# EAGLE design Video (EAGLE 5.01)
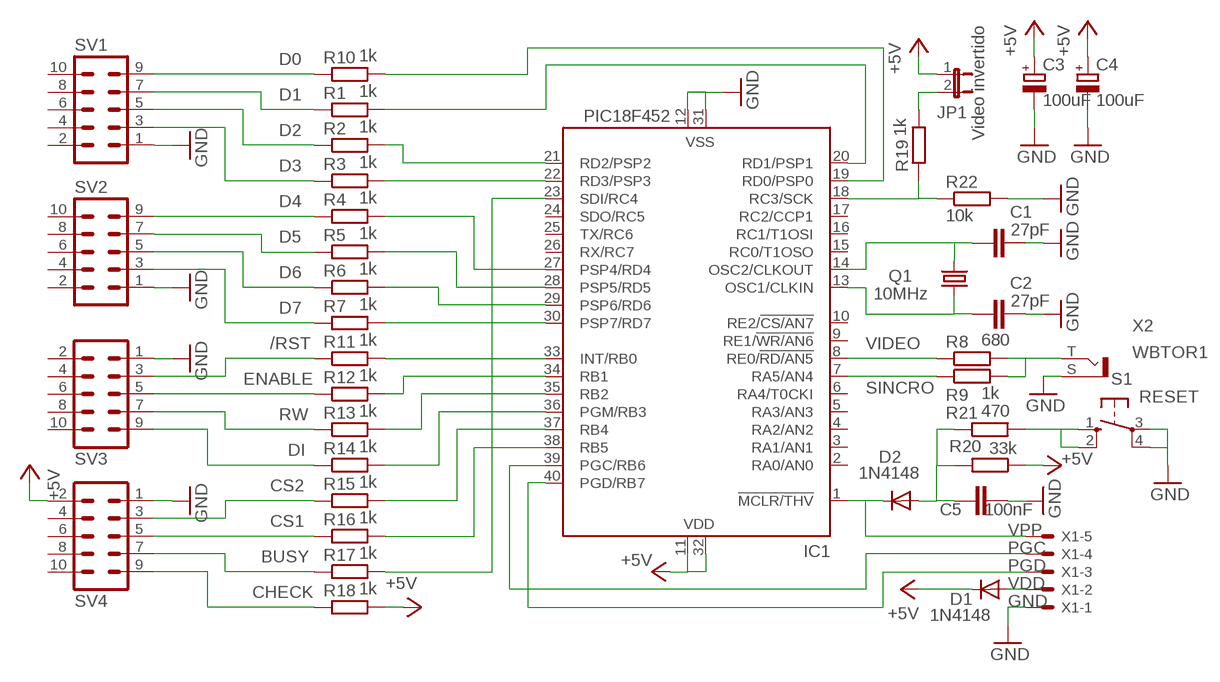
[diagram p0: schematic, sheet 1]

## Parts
C1  27pF  C-EU050-025X075  [C050-025X075]
C2  27pF  C-EU050-025X075  [C050-025X075]
C3  100uF  CPOL-EUE2-5  [E2-5]
C4  100uF  CPOL-EUE2-5  [E2-5]
C5  100nF  C-EU050-025X075  [C050-025X075]
D1  1N4148  [DO35-10]
D2  1N4148  [DO35-10]
IC1  PIC18F452  PIC16F877P  [DIL40]
JP1  Video invertido  JP1E  [JP1]
Q1  10MHz  CRYSTALHC49U-V  [HC49U-V]
R1  1k  R-EU_0207/12  [0207/12]
R2  1k  R-EU_0207/12  [0207/12]
R3  1k  R-EU_0207/12  [0207/12]
R4  1k  R-EU_0207/12  [0207/12]
R5  1k  R-EU_0207/12  [0207/12]
R6  1k  R-EU_0207/12  [0207/12]
R7  1k  R-EU_0207/12  [0207/12]
R8  680  R-EU_0207/12  [0207/12]
R9  1k  R-EU_0207/12  [0207/12]
R10  1k  R-EU_0207/12  [0207/12]
R11  1k  R-EU_0207/12  [0207/12]
R12  1k  R-EU_0207/12  [0207/12]
R13  1k  R-EU_0207/12  [0207/12]
R14  1k  R-EU_0207/12  [0207/12]
R15  1k  R-EU_0207/12  [0207/12]
R16  1k  R-EU_0207/12  [0207/12]
R17  1k  R-EU_0207/12  [0207/12]
R18  1k  R-EU_0207/12  [0207/12]
R19  1k  R-EU_0207/12  [0207/12]
R20  33k  R-EU_0207/12  [0207/12]
R21  470  R-EU_0207/12  [0207/12]
R22  10k  R-EU_0207/12  [0207/12]
S1  RESET  10-XX  [B3F-10XX]
SV1  ML10  [ML10]
SV2  ML10  [ML10]
SV3  ML10  [ML10]
SV4  ML10  [ML10]
X1  22-23-2051  [22-23-2051]
X2  WBTOR1  [WBTOR1]

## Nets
+5V: C3.+ C4.+ D1.C IC1.11(VDD) IC1.32(VDD) JP1.1 R18.2 R20.1 SV4.2
/RST: R11.1 SV3.3
BUSY: R17.1 SV4.7
CHECK: R18.1 SV4.9
CS1: R16.1 SV4.5
CS2: R15.1 SV4.3
D0: R10.1 SV1.9
D1: R1.1 SV1.7
D2: R2.1 SV1.5
D3: R3.1 SV1.3
D4: R4.1 SV2.9
D5: R5.1 SV2.7
D6: R6.1 SV2.5
D7: R7.1 SV2.3
DI: R14.1 SV3.9
ENABLE: R12.1 SV3.5
GND: C1.2 C2.2 C3.- C4.- C5.2 IC1.12(VSS) IC1.31(VSS) R22.2 S1.3(P) S1.4(P1) SV1.1 SV2.1 SV3.1 SV4.1 X1.1 X2.S
N$1: IC1.19(RD0/PSP0) R10.2
N$2: IC1.20(RD1/PSP1) R1.2
N$3: IC1.28(PSP5/RD5) R5.2
N$4: IC1.22(RD3/PSP3) R3.2
N$5: IC1.27(PSP4/RD4) R4.2
N$6: IC1.23(SDI/RC4) R17.2
N$7: IC1.29(PSP6/RD6) R6.2
N$8: IC1.30(PSP7/RD7) R7.2
N$9: IC1.21(RD2/PSP2) R2.2
N$10: C1.1 IC1.14(OSC2/CLKOUT) Q1.2
N$11: IC1.33(INT/RB0) R11.2
N$14: R8.2 R9.2 X2.T
N$15: IC1.34(RB1) R12.2
N$16: IC1.35(RB2) R13.2
N$17: IC1.36(PGM/RB3) R14.2
N$18: IC1.37(RB4) R15.2
N$19: IC1.38(RB5) R16.2
N$20: C2.1 IC1.13(OSC1/CLKIN) Q1.1
N$22: IC1.18(RC3/SCK) R19.1 R22.1
N$23: JP1.2 R19.2
N$27: C5.1 D2.A R20.2 R21.1
N$28: R21.2 S1.1(S) S1.2(S1)
PGC: IC1.39(PGC/RB6) X1.4
PGD: IC1.40(PGD/RB7) X1.3
RW: R13.1 SV3.7
SINCRO: IC1.7(RA5/AN4) R9.1
VDD: D1.A X1.2
VIDEO: IC1.8(RE0/!RD/AN5) R8.1
VPP: D2.C IC1.1(!MCLR/THV) X1.5
Unconnected: IC1.2(RA0/AN0) IC1.3(RA1/AN1) IC1.4(RA2/AN2) IC1.5(RA3/AN3) IC1.6(RA4/T0CKI) IC1.9(RE1/!WR/AN6) IC1.10(RE2/!CS/AN7) IC1.15(RC0/T1OSO) IC1.16(RC1/T1OSI) IC1.17(RC2/CCP1) IC1.24(SDO/RC5) IC1.25(TX/RC6) IC1.26(RX/RC7) SV1.2 SV1.4 SV1.6 SV1.8 SV1.10 SV2.2 SV2.4 SV2.6 SV2.8 SV2.10 SV3.2 SV3.4 SV3.6 SV3.8 SV3.10 SV4.4 SV4.6 SV4.8 SV4.10

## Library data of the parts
C1 C2 = resistor:C-EU: CAPACITOR, European symbol
C3 C4 = resistor:CPOL-EU: POLARIZED CAPACITOR, European symbol
C5 = rcl:C-EU: CAPACITOR, European symbol
D1 D2 = diode:1N4148: DIODE
IC1 = microchip:PIC16F87*: MICROCONTROLLER
JP1 = jumper:JP1E: JUMPER
Q1 = crystal:CRYSTAL: CRYSTAL
R1-R19 R22 = resistor:R-EU_: RESISTOR, European symbol
R20 R21 = rcl:R-EU_: RESISTOR, European symbol
S1 = switch-omron:10-XX: OMRON SWITCH
SV1-SV4 = con-harting-ml:ML10: HARTING
X1 = con-molex:22-23-2051: .100" (2.54mm) Center Header - 5 Pin
X2 = rca:WBTOR1: RCA connectors according to JEITA RC-5231 Cinch

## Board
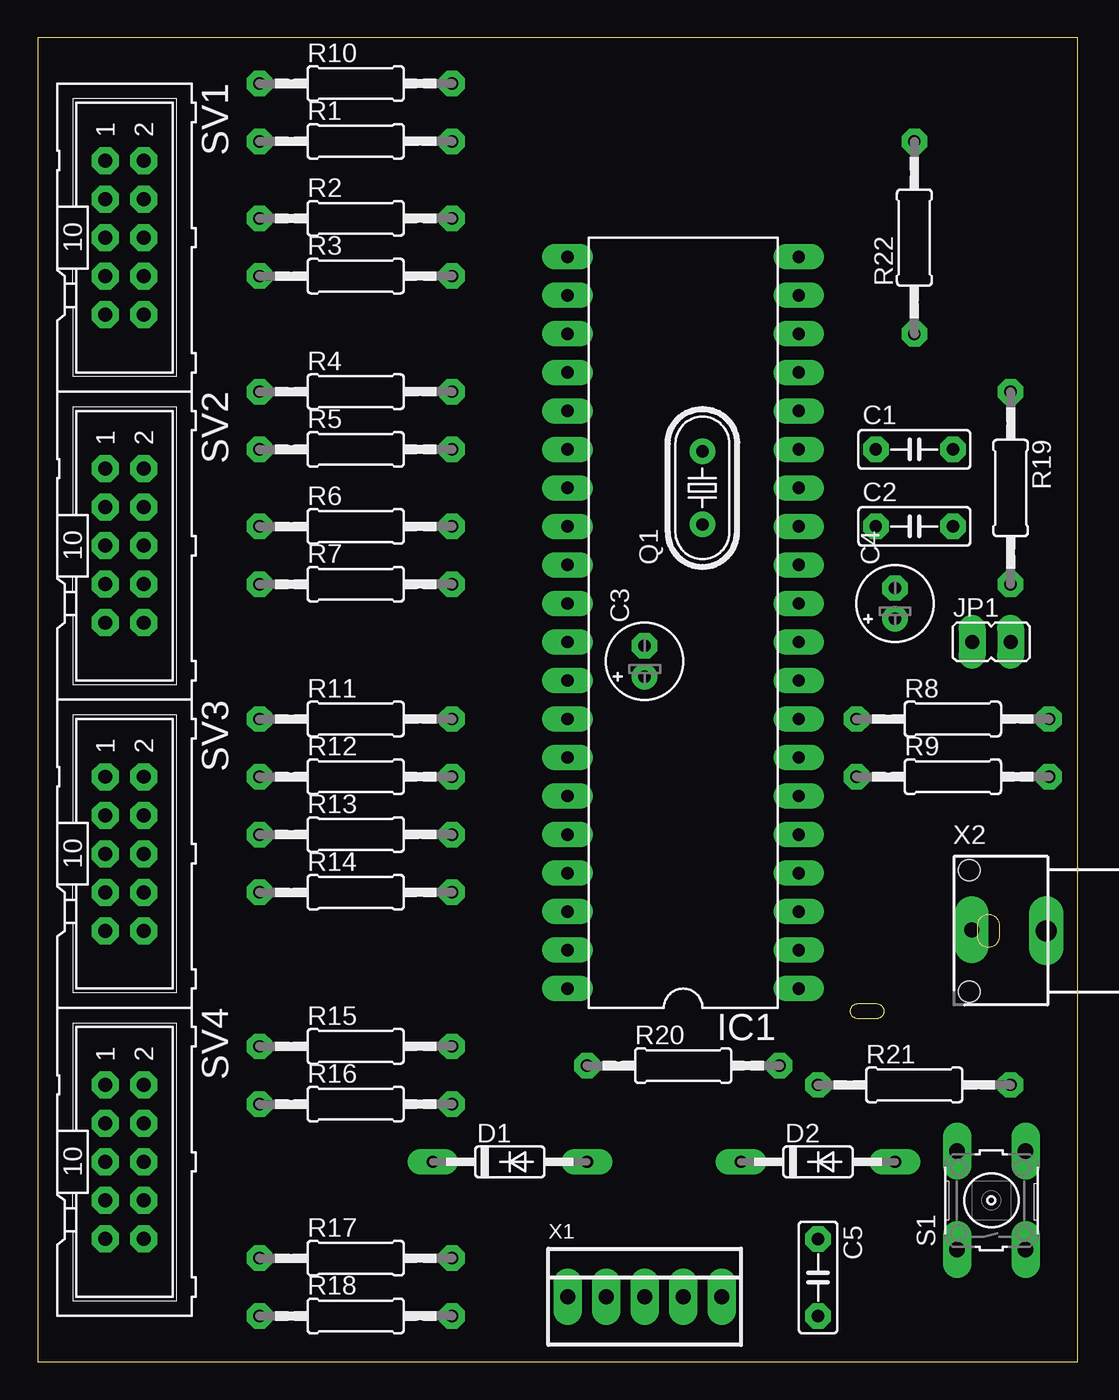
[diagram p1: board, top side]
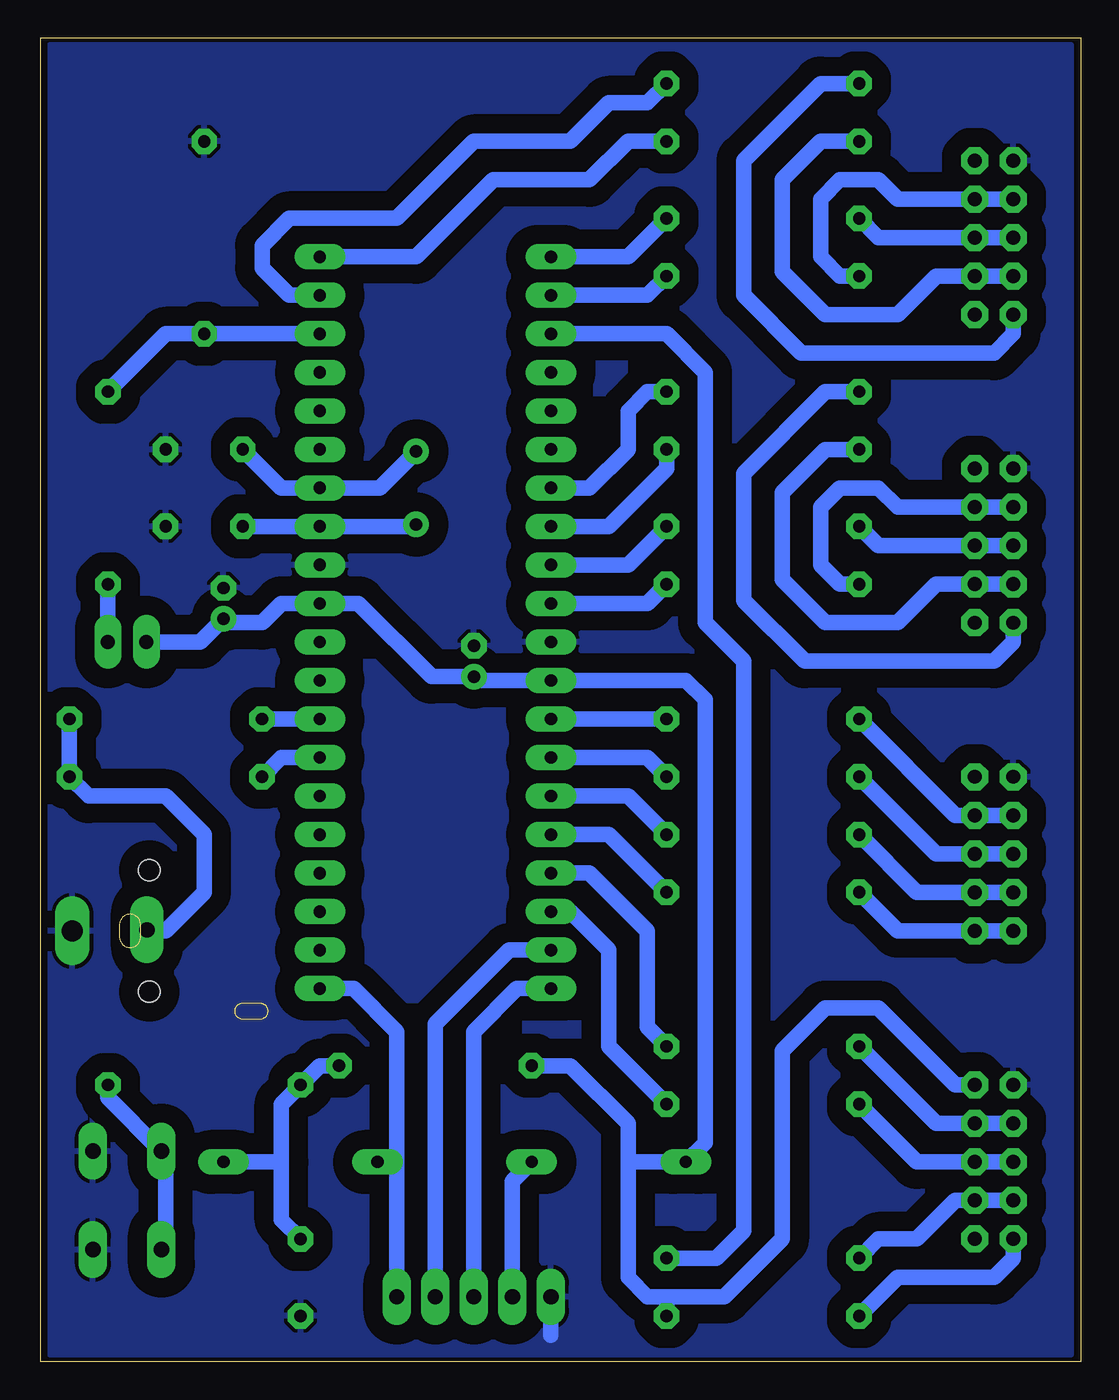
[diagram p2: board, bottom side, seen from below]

Size 68.56 x 87.3 mm. Coordinates in mm from the lower left corner, seen from the top.
Outline: 0,0 68.56,0 68.56,87.3 0,87.3 0,0
Copper layers (1*16): Top 0.035mm / dielectric 1.5mm / Bottom 0.035mm
Design rules "default *": minimum track width 10mil, minimum drill 24mil, track to track 8mil, track to pad 8mil, pad to pad 8mil, via to via 8mil, smd to smd 8mil, copper to edge 0mil, drill to drill 8mil, minimum pad ring 17mil, minimum via ring 8mil, stop-mask expansion 4mil, vias tented up to drill 0mil, thermal gap 10mil

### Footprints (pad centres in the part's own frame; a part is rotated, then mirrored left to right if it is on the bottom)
C050-025X075 = drill 0.813 octagon: 1 -2.54,0; 2 2.54,0
E2-5 = drill 0.813 pad 1.27 round: + -1.016,0 | drill 0.813 pad 1.27 octagon: - 1.016,0
DO35-10 = drill 0.813 long: A 5.08,0; C -5.08,0
DIL40 = drill 0.813 long: 1 -24.13,-7.62; 2 -21.59,-7.62; 3 -19.05,-7.62; 4 -16.51,-7.62; 5 -13.97,-7.62; 6 -11.43,-7.62; 7 -8.89,-7.62; 8 -6.35,-7.62; 9 -3.81,-7.62; 10 -1.27,-7.62; 11 1.27,-7.62; 12 3.81,-7.62; 13 6.35,-7.62; 14 8.89,-7.62; 15 11.43,-7.62; 16 13.97,-7.62; 17 16.51,-7.62; 18 19.05,-7.62; 19 21.59,-7.62; 20 24.13,-7.62; 21 24.13,7.62; 22 21.59,7.62; 23 19.05,7.62; 24 16.51,7.62; 25 13.97,7.62; 26 11.43,7.62; 27 8.89,7.62; 28 6.35,7.62; 29 3.81,7.62; 30 1.27,7.62; 31 -1.27,7.62; 32 -3.81,7.62; 33 -6.35,7.62; 34 -8.89,7.62; 35 -11.43,7.62; 36 -13.97,7.62; 37 -16.51,7.62; 38 -19.05,7.62; 39 -21.59,7.62; 40 -24.13,7.62
JP1 = drill 0.914 long: 1 0,-1.27; 2 0,1.27
HC49U-V = drill 0.813 round: 1 -2.413,0; 2 2.413,0
0207/12 = drill 0.813 octagon: 1 -6.35,0; 2 6.35,0
B3F-10XX = drill 1.016 long: 1 -3.251,2.261; 2 3.251,2.261; 3 -3.251,-2.261; 4 3.251,-2.261
ML10 = drill 0.914 octagon: 1 -5.08,-1.27; 2 -5.08,1.27; 3 -2.54,-1.27; 4 -2.54,1.27; 5 0,-1.27; 6 0,1.27; 7 2.54,-1.27; 8 2.54,1.27; 9 5.08,-1.27; 10 5.08,1.27
22-23-2051 = drill 1 long: 1 -5.08,0; 2 -2.54,0; 3 0,0; 4 2.54,0; 5 5.08,0
WBTOR1 = drill 1.4 pad 2.2 long: S 0,-0.19 | drill 1 pad 2.2 long: T -0.065,-5.114 | hole 1.4: -4.004,-5.27; 4.004,-5.27

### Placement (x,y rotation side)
C1  57.78,60.16 0 top
C2  57.78,55.08 0 top
C3  40,46.19 90 top
C4  56.51,50 90 top
C5  51.43,5.55 270 top
D1  31.11,13.17 0 top
D2  51.43,13.17 0 top
IC1  42.54,48.73 90 top
JP1  62.86,47.46 270 top
Q1  43.81,57.62 90 top
R1  20.95,80.48 0 top
R2  20.95,75.4 0 top
R3  20.95,71.59 0 top
R4  20.95,63.97 0 top
R5  20.95,60.16 0 top
R6  20.95,55.08 0 top
R7  20.95,51.27 0 top
R8  60.32,42.38 0 top
R9  60.32,38.57 0 top
R10  20.95,84.29 0 top
R11  20.95,42.38 0 top
R12  20.95,38.57 0 top
R13  20.95,34.76 0 top
R14  20.95,30.95 0 top
R15  20.95,20.79 0 top
R16  20.95,16.98 0 top
R17  20.95,6.82 0 top
R18  20.95,3.01 0 top
R19  64.13,57.62 270 top
R20  42.54,19.52 0 top
R21  57.78,18.25 0 top
R22  57.78,74.13 90 top
S1  62.86,10.63 90 top
SV1  5.71,74.13 270 top
SV2  5.71,53.81 270 top
SV3  5.71,33.49 270 top
SV4  5.71,13.17 270 top
X1  40,4.28 0 top
X2  66.67,28.41 270 top

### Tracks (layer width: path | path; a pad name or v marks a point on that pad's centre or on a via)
+5V
  Bottom 1.016: 29.84,13.17 29.84,5.55 28.57,4.28 27.3,4.28 | 29.84,13.17 29.84,15.71 33.65,19.52 R20.1 | 27.3,4.28 23.49,4.28 19.68,8.09 19.68,20.49 16.84,23.33 13.33,23.33 8.25,18.25 SV4.2 | 27.3,4.28 R18.2 | 29.84,13.17 D1.C 24.76,14.44 24.76,43.65 26.03,44.92 IC1.32 39.75,44.92 C3.+ 42.79,45.17 47.62,50 IC1.11 52.7,50 53.97,48.73 56.26,48.73 C4.+ 58.03,47.46 JP1.1
/RST
  Bottom 1.016: SV3.3 8.25,36.03 R11.1
BUSY
  Bottom 1.016: R17.1 13.33,8.09 10.79,8.09 8.25,10.63 SV4.7
CHECK
  Bottom 1.016: R18.1 12.06,5.55 5.71,5.55 4.44,6.82 SV4.9
CS1
  Bottom 1.016: R16.1 10.79,13.17 SV4.5
CS2
  Bottom 1.016: SV4.3 9.52,15.71 R15.1
D0
  Bottom 1.016: SV1.9 4.44,67.78 5.71,66.51 18.41,66.51 22.22,70.32 22.22,79.21 17.14,84.29 R10.1
D1
  Bottom 1.016: R1.1 17.14,80.48 19.68,77.94 19.68,71.89 16.84,69.05 12.06,69.05 9.52,71.59 SV1.7
D2
  Bottom 1.016: R2.1 13.33,74.13 SV1.5
D3
  Bottom 1.016: R3.1 15.87,71.59 17.14,72.86 17.14,76.67 15.87,77.94 13.33,77.94 12.06,76.67 SV1.3
D4
  Bottom 1.016: R4.1 16.83,63.97 22.22,58.58 22.22,50.21 18.2,46.19 5.71,46.19 4.44,47.46 SV2.9
D5
  Bottom 1.016: SV2.7 9.52,51.27 12.06,48.73 16.84,48.73 19.68,51.57 19.68,57.32 16.84,60.16 R5.1
D6
  Bottom 1.016: SV2.5 13.33,53.81 R6.1
D7
  Bottom 1.016: SV2.3 12.06,56.35 13.33,57.62 15.87,57.62 17.14,56.35 17.14,52.54 15.87,51.27 R7.1
DI
  Bottom 1.016: R14.1 12.06,28.41 SV3.9
ENABLE
  Bottom 1.016: SV3.5 9.52,33.49 R12.1
GND
  Bottom 1.016: 34.92,1.74 X1.1
  pour Bottom (isolate 1.27): 0.63,86.83 67.94,86.83 67.94,0.47 0.63,0.47
N$1
  Bottom 1.016: IC1.19 52.17,70.32 53.97,72.12 53.97,73.6 52.17,75.4 45.08,75.4 40,80.48 33.65,80.48 31.11,83.02 28.57,83.02 R10.2
N$2
  Bottom 1.016: IC1.20 43.81,72.86 38.73,77.94 32.38,77.94 29.84,80.48 R1.2
N$3
  Bottom 1.016: R5.2 27.3,58.89 31.11,55.08 IC1.28
N$4
  Bottom 1.016: IC1.22 28.57,70.32 R3.2
N$5
  Bottom 1.016: IC1.27 32.38,57.62 29.84,60.16 29.84,62.7 28.57,63.97 R4.2
N$6
  Bottom 1.016: IC1.23 27.3,67.78 24.76,65.24 24.76,48.73 22.22,46.19 22.22,8.62 24.02,6.82 R17.2
N$7
  Bottom 1.016: R6.2 29.84,52.54 IC1.29
N$8
  Bottom 1.016: IC1.30 28.57,50 R7.2
N$9
  Bottom 1.016: R2.2 29.84,72.86 IC1.21
N$10
  Bottom 1.016: Q1.2 46.22,57.62 IC1.14 52.7,57.62 C1.1
N$11
  Bottom 1.016: R11.2 IC1.33
N$14
  Bottom 1.016: R8.2 R9.2 65.4,37.3 60.32,37.3 57.78,34.76 57.78,30.95 60.32,28.41 61.59,28.41 61.59,28.44 X2.T
N$15
  Bottom 1.016: R12.2 28.57,39.84 IC1.34
N$16
  Bottom 1.016: R13.2 29.84,37.3 IC1.35
N$17
  Bottom 1.016: R14.2 31.11,34.76 IC1.36
N$18
  Bottom 1.016: IC1.37 32.38,32.22 28.57,28.41 28.57,22.06 R15.2
N$19
  Bottom 1.016: IC1.38 33.65,29.68 31.11,27.14 31.11,20.79 R16.2
N$20
  Bottom 1.016: Q1.1 43.94,55.08 IC1.13 C2.1
N$22
  Bottom 1.016: IC1.18 R22.1 60.32,67.78 R19.1
N$23
  Bottom 1.016: JP1.2 R19.2
N$27
  Bottom 1.016: C5.1 52.7,9.36 52.7,13.17 | 52.7,13.17 52.7,16.98 R21.1 50.16,19.52 R20.2 | 52.7,13.17 D2.A
N$28
  Bottom 1.016: S1.1 60.32,7.66 60.32,13.6 S1.2 64.13,17.41 R21.2
N$45
  pour Bottom (isolate 1.27): 14.6,79.21 56.51,79.21 56.51,8.09 14.6,8.09
PGC
  Bottom 1.016: X1.4 42.54,22.28 37.68,27.14 IC1.39
PGD
  Bottom 1.016: X1.3 40,21.76 37.16,24.6 IC1.40
RW
  Bottom 1.016: SV3.7 10.79,30.95 R13.1
SINCRO
  Bottom 1.016: R9.1 52.7,39.84 IC1.7
VDD
  Bottom 1.016: X1.2 37.46,11.9 D1.A
VIDEO
  Bottom 1.016: IC1.8 R8.1
VPP
  Bottom 1.016: X1.5 45.08,13.17 | 45.08,13.17 45.08,21.76 47.92,24.6 IC1.1 | 45.08,13.17 D2.C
